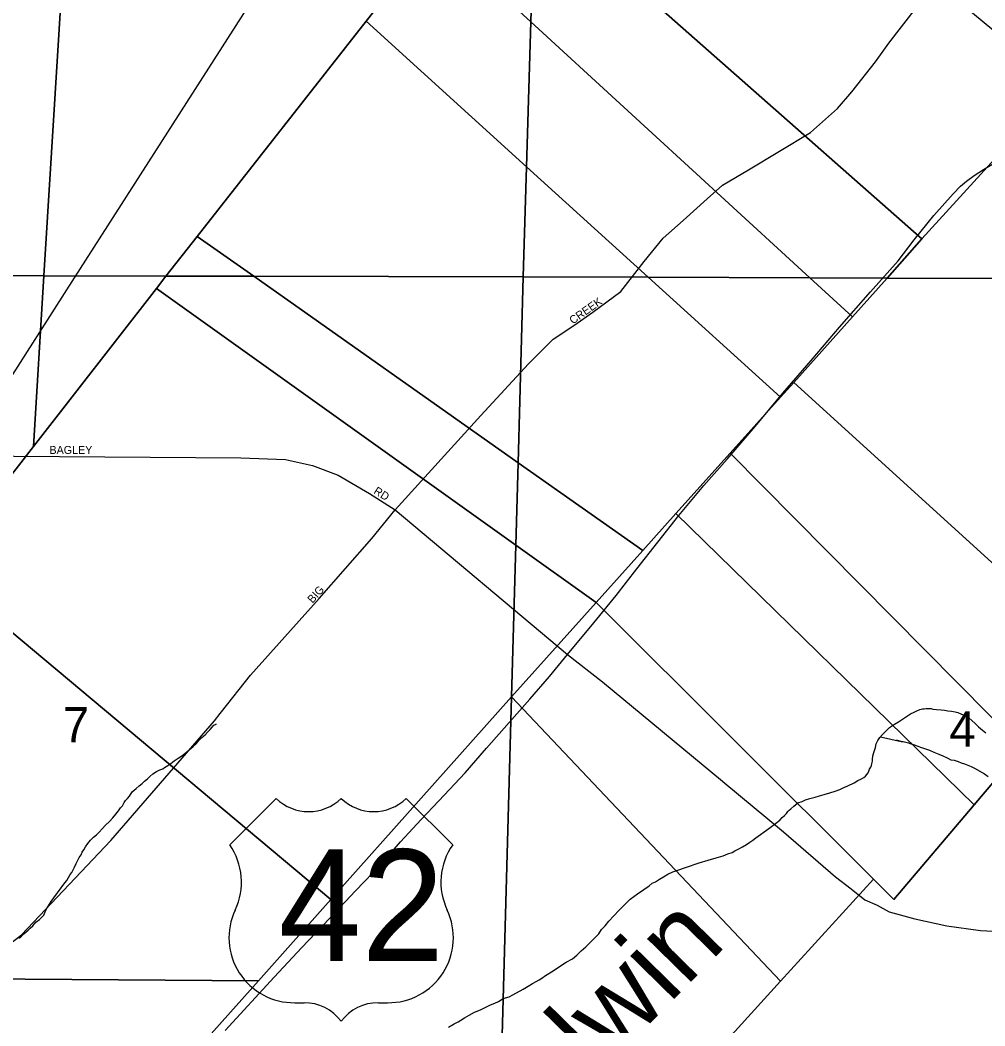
# Model space of a CAD drawing. Extents: x 2010165 to 2382125, y 1060529 to 1407316.
# Drawn here: x 2156190 to 2162213, y 1225499 to 1231781 of the extents above; entities that cross this region are included whole.
import ezdxf

# ---------------------------------------------------------------- set-up
doc = ezdxf.new("R2010")
doc.units = 0
for name, color, linetype in [('GM_X_City_Street', 7, 'Continuous'), ('GM_X_City_Street_Text', 7, 'Continuous'), ('GM_X_Minor_River', 7, 'Continuous'), ('GM_X_Minor_River_Text', 7, 'Continuous'), ('GM_X_Rail_Line', 7, 'Continuous'), ('GM_X_Section', 7, 'Continuous'), ('GM_X_Section_Text', 7, 'Continuous'), ('GM_X_US_Location', 7, 'Continuous'), ('GM_X_US_Route', 7, 'Continuous'), ('GM_X_US_Shield', 7, 'Continuous')]:
    doc.layers.add(name, color=color, linetype=linetype)

msp = doc.modelspace()

# ---------------------------------------------------------------- linework, layer by layer
at = {"layer": 'GM_X_City_Street'}
for points in [[(2162868.4, 1231219), (2161945, 1231985), (2159433.3, 1234116.7), (2159331.7, 1234201.2), (2159308.2, 1234295.5), (2159312.2, 1234628.9)], [(2158532.2, 1228721.7), (2159067.2, 1229312.4), (2159364.5, 1229634.1), (2159517.2, 1229787.9), (2159646.5, 1229873.4), (2159765.8, 1229956.7), (2159940.7, 1230086.7), (2160085.1, 1230272.6), (2160205.5, 1230420.1), (2160330.4, 1230530.2), (2160478.6, 1230665.5), (2160575.8, 1230750.5), (2160736.6, 1230846.7), (2161125.6, 1231078.8), (2161292.5, 1231230.1), (2161383.6, 1231333.3), (2161529.4, 1231521.5), (2161614.5, 1231636.9), (2161785.5, 1231859.7)], [(2155300.7, 1229064.8), (2157567.5, 1229047.7), (2157845.6, 1229036.3), (2158015.9, 1228999.7), (2158174.4, 1228939), (2158371.4, 1228824.5), (2158532.2, 1228721.7), (2159607.8, 1227818.3)], [(2157447.3, 1227460.9), (2157629, 1227690.4), (2158056.9, 1228169.7), (2158385.7, 1228543.8), (2158532.2, 1228721.7)], [(2159607.8, 1227818.3), (2159825.2, 1227648.6), (2160575.7, 1227027.8), (2160577.2, 1227026.5)], [(2154223.5, 1224477), (2154223.5, 1224477), (2154349.7, 1224803), (2154466.7, 1225003.3), (2154573.1, 1225171.7), (2154728.5, 1225408.9), (2154883.1, 1225544.5), (2154998.2, 1225623.4), (2155146.2, 1225694.6), (2155257.3, 1225724.1), (2155928.2, 1225891.4), (2156067.7, 1225965.8), (2156198.3, 1226068.3), (2156755.8, 1226656.4), (2157403.4, 1227405.5), (2157439.3, 1227450.9), (2157447.3, 1227460.9)], [(2160577.2, 1227026.5), (2160957, 1226712.3), (2161281.4, 1226430.6), (2161378, 1226355.2), (2161464.6, 1226285.8), (2161540.9, 1226252.4), (2161615.2, 1226211), (2161775.6, 1226168.4), (2161976, 1226124.1), (2162186.2, 1226096), (2162428.3, 1226082.2), (2162702.2, 1226094.8), (2164457.5, 1226169.3), (2164865.3, 1226193.2)]]:
    msp.add_lwpolyline(points, dxfattribs=at)
at = {"layer": 'GM_X_Minor_River'}
for points in [[(2160206.1, 1226429.7), (2160234, 1226446.1), (2160265.8, 1226460.5), (2160301.7, 1226475), (2160343.6, 1226487.6), (2160429.4, 1226516.7), (2160485.3, 1226533.4), (2160535.2, 1226548.1), (2160579.1, 1226560.6), (2160609, 1226573.1), (2160634.9, 1226581.4), (2160652.8, 1226593.6), (2160676.7, 1226606), (2160700.5, 1226618.3), (2160724.4, 1226632.6), (2160746.2, 1226647), (2160764.1, 1226659.2), (2160784, 1226673.5), (2160865.3, 1226732.7), (2160907, 1226763.3), (2160932.8, 1226783.7), (2160948.6, 1226799.9), (2160962.4, 1226814.1), (2160974.3, 1226826.3), (2160982.2, 1226838.4), (2160992.1, 1226846.6), (2161002, 1226854.8), (2161019.8, 1226871), (2161045.6, 1226893.4), (2161073.5, 1226901.8), (2161093.4, 1226912.1), (2161121.3, 1226920.4), (2161153.3, 1226928.8), (2161181.2, 1226935.2), (2161209.2, 1226943.6), (2161245.1, 1226954), (2161279, 1226964.5), (2161307, 1226974.8), (2161332.8, 1226987.2), (2161358.7, 1226999.6), (2161396.5, 1227018.1), (2161420.4, 1227032.4), (2161442.3, 1227042.7), (2161458.2, 1227050.9), (2161468.1, 1227059.1), (2161476, 1227069.2), (2161483.9, 1227079.3), (2161489.8, 1227089.5), (2161493.6, 1227103.5), (2161501.5, 1227115.7), (2161505.3, 1227125.8), (2161507.2, 1227135.8), (2161511, 1227151.9), (2161510.8, 1227163.9), (2161514.6, 1227186.1), (2161522.2, 1227212.2), (2161529.9, 1227238.4), (2161535.6, 1227260.6), (2161545.4, 1227280.8), (2161557.1, 1227301), (2161574.9, 1227319.2), (2161590.7, 1227335.5), (2161618.4, 1227363.9), (2161648.2, 1227384.3), (2161674.1, 1227398.7), (2161749.5, 1227447.8), (2161771.5, 1227458.1), (2161789.4, 1227466.3), (2161807.3, 1227474.6), (2161823.3, 1227478.8), (2161835.3, 1227478.9), (2161847.3, 1227481.1), (2161865.3, 1227481.3), (2161877.3, 1227481.4), (2161889.4, 1227477.6), (2161911.5, 1227475.8), (2161939.5, 1227474.2), (2161961.6, 1227470.4), (2161981.7, 1227466.7), (2162005.8, 1227465), (2162027.9, 1227461.2), (2162043.9, 1227457.4), (2162064.1, 1227447.6), (2162092.3, 1227435.9), (2162112.5, 1227424.1), (2162132.8, 1227406.3), (2162153, 1227388.5), (2162173.4, 1227366.7), (2162197.7, 1227346.9), (2162219.9, 1227329.1)], [(2156966.7, 1227028.2), (2156984.6, 1227042.4), (2157000.4, 1227056.7), (2157018.2, 1227073), (2157040.1, 1227087.3), (2157061.9, 1227099.6), (2157079.9, 1227105.8), (2157091.8, 1227114), (2157111.7, 1227126.3), (2157129.6, 1227138.5), (2157151.4, 1227154.8), (2157177.2, 1227171.2), (2157199.1, 1227185.5), (2157218.9, 1227199.8), (2157270.4, 1227244.6), (2157288.2, 1227260.8), (2157306, 1227281.1), (2157323.8, 1227301.4), (2157345.6, 1227317.7), (2157361.4, 1227336), (2157377.2, 1227350.2), (2157389.1, 1227364.4), (2157398.9, 1227376.6), (2157412.8, 1227384.8), (2157410.8, 1227384.7), (2157410.9, 1227382.7)], [(2161561, 1227305), (2161689.7, 1227276.5), (2161661.5, 1227284.2), (2161689.7, 1227276.5), (2161703.7, 1227274.6), (2161719.8, 1227270.8), (2161735.9, 1227267), (2161752, 1227261.2), (2161774.1, 1227255.4), (2161794.3, 1227245.7), (2161818.4, 1227237.9), (2161842.6, 1227230.2), (2161866.7, 1227220.5), (2161894.9, 1227208.8), (2161925.1, 1227197.1), (2161951.3, 1227185.4), (2161977.5, 1227173.7), (2162001.7, 1227161.9), (2162021.8, 1227158.1), (2162045.9, 1227150.4), (2162066.1, 1227142.6), (2162086.2, 1227136.9), (2162106.4, 1227127.1), (2162128.5, 1227119.3), (2162148.7, 1227109.6), (2162211.2, 1227074.2), (2162233.5, 1227056.4)], [(2156182.2, 1226047.4), (2156198, 1226059.7), (2156211.9, 1226073.9), (2156227.7, 1226086.1), (2156239.6, 1226096.3), (2156251.5, 1226110.5), (2156269.3, 1226124.8), (2156287, 1226147.1), (2156310.9, 1226163.4), (2156324.7, 1226177.6), (2156338.5, 1226191.8), (2156342.4, 1226201.9), (2156352.1, 1226226.1), (2156383.5, 1226276.6), (2156399.3, 1226298.9), (2156468.2, 1226392.1), (2156482, 1226408.3), (2156491.7, 1226426.4), (2156501.5, 1226444.6), (2156511.4, 1226456.8), (2156521.2, 1226473), (2156529, 1226491.1), (2156538.7, 1226513.3), (2156548.5, 1226529.5), (2156558.2, 1226551.7), (2156570, 1226567.9), (2156577.8, 1226584), (2156587.7, 1226598.2), (2156597.4, 1226618.4), (2156613.2, 1226638.6), (2156629, 1226658.9), (2156646.7, 1226677.1), (2156666.6, 1226693.4), (2156682.4, 1226709.7), (2156702.1, 1226730), (2156721.9, 1226752.3), (2156747.6, 1226776.7), (2156767.4, 1226799), (2156787.1, 1226821.3), (2156802.9, 1226841.6), (2156816.6, 1226861.8), (2156828.5, 1226874), (2156840.2, 1226894.2), (2156848.1, 1226906.3), (2156860, 1226918.5), (2156871.8, 1226934.7), (2156889.5, 1226961), (2156913.2, 1226981.4), (2156933.1, 1226997.7), (2156950.9, 1227013.9), (2156966.7, 1227028.2)], [(2158864, 1225492.3), (2158899.8, 1225512.8), (2158923.7, 1225525.1), (2158941.6, 1225535.4), (2158963.5, 1225549.7), (2158993.3, 1225566.1), (2159027.1, 1225584.6), (2159065, 1225599.1), (2159096.8, 1225615.5), (2159126.7, 1225630), (2159152.6, 1225640.3), (2159176.5, 1225652.6), (2159206.3, 1225671.1), (2159242.2, 1225681.5), (2159266.1, 1225693.8), (2159329.8, 1225728.8), (2159361.6, 1225747.2), (2159389.4, 1225763.6), (2159411.3, 1225775.9), (2159431.2, 1225786.2), (2159447.1, 1225798.4), (2159470.9, 1225814.7), (2159518.6, 1225843.4), (2159558.3, 1225870), (2159600, 1225896.6), (2159637.8, 1225919.1), (2159665.6, 1225941.5), (2159693.3, 1225967.9), (2159721, 1225992.4), (2159742.7, 1226014.7), (2159762.5, 1226035), (2159784.3, 1226055.3), (2159802.1, 1226073.6), (2159819.7, 1226101.9), (2159843.5, 1226124.3), (2159865.2, 1226152.6), (2159896.8, 1226187.1), (2159928.4, 1226219.6), (2159960, 1226252.1), (2159999.6, 1226290.7), (2160045.3, 1226323.4), (2160082.9, 1226351.9), (2160116.7, 1226374.4), (2160136.5, 1226390.7), (2160156.5, 1226399), (2160182.3, 1226415.3), (2160206.1, 1226429.7)]]:
    msp.add_lwpolyline(points, dxfattribs=at)
at = {"layer": 'GM_X_Rail_Line'}
msp.add_lwpolyline([(2152659, 1224128.4), (2152739.6, 1224246.9), (2152909.8, 1224516.9), (2153135.7, 1224869.5), (2153696.1, 1225746.1), (2153852.4, 1225988.7), (2154336.9, 1226746.4), (2154804.9, 1227475), (2154949.8, 1227703.5), (2155203.2, 1228100.3), (2155761.5, 1228971.2), (2156480.3, 1230096.1), (2157742.6, 1232068.2), (2160262.5, 1236005.3), (2160720.5, 1236722.8), (2161364.8, 1237726.8), (2162140.1, 1238942.9), (2162984.3, 1240258.6), (2165607, 1244357.2), (2165822.2, 1244694.3), (2166159.2, 1245221.1), (2166502.4, 1245756.1), (2166780.6, 1246192.6), (2167540, 1247377.8)], dxfattribs=at)
at = {"layer": 'GM_X_Section'}
for points in [[(2159417.7, 1233134.5), (2159997.2, 1233872.9), (2163015.7, 1231555.2), (2162360.8, 1231008.9), (2161818.7, 1230414.8), (2159400.5, 1232548.2)], [(2159138.7, 1232779.1), (2159400.5, 1232548.2), (2159377.7, 1231770.4), (2158778.4, 1232320)], [(2159377.7, 1231770.4), (2159400.5, 1232548.2), (2161818.7, 1230414.8), (2161604.3, 1230169.9), (2161121.1, 1230171.6)], [(2158620.5, 1232118.8), (2158778.4, 1232320), (2159377.7, 1231770.4), (2159351.2, 1230865.6), (2158350.2, 1231774.5)], [(2156456.2, 1232094.9), (2158620.5, 1232118.8), (2158350.2, 1231774.5), (2157294.8, 1230429.8), (2157100.3, 1230181.9), (2156338.3, 1230183.2)], [(2154026.7, 1232068), (2156456.2, 1232094.9), (2156338.3, 1230183.2), (2153937.9, 1230187.4)], [(2158350.2, 1231774.5), (2159351.2, 1230865.6), (2159331, 1230177.9), (2157647.8, 1230180.9), (2157294.8, 1230429.8)], [(2159351.2, 1230865.6), (2159377.7, 1231770.4), (2161121.1, 1230171.6), (2160111.4, 1230175.2)], [(2161818.7, 1230414.8), (2162360.8, 1231008.9), (2163222.3, 1230164.2), (2161604.3, 1230169.9)], [(2159331, 1230177.9), (2159351.2, 1230865.6), (2160111.4, 1230175.2)], [(2157294.8, 1230429.8), (2157647.8, 1230180.9), (2157100.3, 1230181.9)], [(2153937.9, 1230187.4), (2156338.3, 1230183.2), (2156272.6, 1229118.6), (2155759.2, 1228459.1), (2155751, 1228281.1), (2155636.1, 1225795.5), (2157678.6, 1225781.7), (2157120.7, 1225155.3), (2156676.4, 1224704.2), (2153680, 1224728.2)], [(2156338.3, 1230183.2), (2157100.3, 1230181.9), (2157040.2, 1230104.6), (2156272.6, 1229118.6)], [(2157100.3, 1230181.9), (2157647.8, 1230180.9), (2159298.8, 1229016.9), (2159284.5, 1228500.8), (2157040.2, 1230104.6)], [(2157647.8, 1230180.9), (2159331, 1230177.9), (2159298.8, 1229016.9)], [(2159331, 1230177.9), (2160111.4, 1230175.2), (2160936.8, 1229425.7), (2160623, 1229076), (2160284.7, 1228699), (2160077.4, 1228468), (2159298.8, 1229016.9)], [(2160111.4, 1230175.2), (2161121.1, 1230171.6), (2161387.2, 1229927.5), (2161019.8, 1229518.1), (2160936.8, 1229425.7)], [(2161604.3, 1230169.9), (2163222.3, 1230164.2), (2164163.6, 1229262.5), (2162917.8, 1227792.4), (2161019.8, 1229518.1), (2161387.2, 1229927.5)], [(2161121.1, 1230171.6), (2161604.3, 1230169.9), (2161387.2, 1229927.5)], [(2157040.2, 1230104.6), (2159284.5, 1228500.8), (2159258.2, 1227553.7), (2158130.5, 1226289.2), (2155751, 1228281.1), (2155759.2, 1228459.1), (2156272.6, 1229118.6)], [(2164892.6, 1229601.3), (2164886.4, 1228716.3), (2164890.7, 1226190.3), (2164893.3, 1224650.6), (2161969.6, 1224667.8), (2159940.1, 1224679.7), (2160937.9, 1225778.1), (2161517.6, 1226416), (2161645.8, 1226288.2), (2162145.6, 1226879.2), (2162446.4, 1227234.8), (2162917.8, 1227792.4), (2164163.6, 1229262.5), (2164602, 1229623.7)], [(2161019.8, 1229518.1), (2162917.8, 1227792.4), (2162446.4, 1227234.8), (2160623, 1229076), (2160936.8, 1229425.7)], [(2160623, 1229076), (2162446.4, 1227234.8), (2162145.6, 1226879.2), (2160284.7, 1228699)], [(2159298.8, 1229016.9), (2160077.4, 1228468), (2159785.5, 1228142.8), (2159284.5, 1228500.8)], [(2160284.7, 1228699), (2162145.6, 1226879.2), (2161645.8, 1226288.2), (2161517.6, 1226416), (2159785.5, 1228142.8), (2160077.4, 1228468)], [(2159785.5, 1228142.8), (2159258.2, 1227553.7), (2159284.5, 1228500.8)], [(2158130.5, 1226289.2), (2157678.6, 1225781.7), (2155636.1, 1225795.5), (2155751, 1228281.1)], [(2159785.5, 1228142.8), (2161517.6, 1226416), (2160937.9, 1225778.1), (2159258.2, 1227553.7)], [(2159258.2, 1227553.7), (2159178.7, 1224684.2), (2157758.6, 1224695.5), (2157120.7, 1225155.3), (2157678.6, 1225781.7), (2158130.5, 1226289.2)], [(2159258.2, 1227553.7), (2160937.9, 1225778.1), (2159940.1, 1224679.7), (2159178.7, 1224684.2)]]:
    msp.add_lwpolyline(points, close=True, dxfattribs=at)
at = {"layer": 'GM_X_US_Route'}
for points in [[(2159607.8, 1227818.3), (2159771.1, 1228017.5), (2159910.6, 1228186.6), (2160040.1, 1228353.5), (2160303, 1228687.6), (2160458.4, 1228874.7), (2160603.9, 1229039.8), (2160779.2, 1229243.1), (2160952.6, 1229450.4), (2161128, 1229655.7), (2161305.3, 1229863), (2161498.6, 1230084.4), (2161671.2, 1230278.6), (2161771, 1230409.3), (2161894.7, 1230560), (2162014.5, 1230696.8), (2162060.4, 1230745), (2162098.4, 1230775.2), (2162146.4, 1230811.5), (2162204.4, 1230847.8), (2162298.4, 1230904.2), (2162480.4, 1231003.1), (2162676.4, 1231110), (2162868.4, 1231219)], [(2157469.1, 1225470.7), (2157776, 1225803.1), (2157949.4, 1225988.4), (2158120.8, 1226169.6), (2158284.3, 1226342.7), (2158447.8, 1226513.9), (2158565.4, 1226648.7), (2158693, 1226787.6), (2158804.6, 1226904.4), (2158968.1, 1227079.6), (2159101.6, 1227234.6), (2159243.1, 1227393.6), (2159372.6, 1227540.5), (2159494.2, 1227681.4), (2159607.8, 1227818.3)]]:
    msp.add_lwpolyline(points, dxfattribs=at)
at = {"layer": 'GM_X_US_Shield'}
for p, q in [((2157788.2, 1226920.3), (2157498.2, 1226630.2)), ((2158890.4, 1226630.2), (2158600.3, 1226920.3)), ((2157904.2, 1225644.1), (2157962.2, 1225644.1)), ((2158426.3, 1225644.1), (2158484.3, 1225644.1))]:
    msp.add_line(p, q, dxfattribs=at)
for centre, radius, start, end in [((2157991.2, 1227127.4), 290, 225.573, 314.427), ((2158397.3, 1227127.4), 290, 225.573, 314.427), ((2157165.5, 1226397.3), 406.1, 334.54712, 35.00093), ((2159223, 1226397.3), 406.1, 144.99907, 205.45288), ((2157899.7, 1226050.1), 406.1, 154.83192, 270.63826), ((2158488.8, 1226050.1), 406.1, 269.36174, 25.16808), ((2157962.2, 1225354.1), 290, 36.8699, 90), ((2158426.3, 1225354.1), 290, 90, 143.1301)]:
    msp.add_arc(centre, radius, start, end, dxfattribs=at)

# ---------------------------------------------------------------- texts
at = {"layer": 'GM_X_City_Street_Text'}
for s, rotation, p in [('CREEK', 35.39409, (2159640.9, 1229879.3)), ('BAGLEY', 0.00001, (2156372.7, 1229071.4)), ('RD', 327.98725, (2158392.8, 1228827.9)), ('BIG', 48.18016, (2158015.6, 1228135.4))]:
    msp.add_text(s, height=50, rotation=rotation, dxfattribs=at).set_placement(p)
at = {"layer": 'GM_X_Minor_River_Text'}
msp.add_text('Baldwin', height=500.28, rotation=45.53118, dxfattribs=at).set_placement((2158965.5, 1224334.8))
at = {"layer": 'GM_X_Section_Text'}
for s, p in [('7', (2156456.3, 1227269.9)), ('4', (2161991.5, 1227242.3))]:
    msp.add_text(s, height=221, rotation=0.00001, dxfattribs=at).set_placement(p)
at = {"layer": 'GM_X_US_Location'}
for s in ['/', '0']:
    msp.add_text(s, height=1, dxfattribs=at).set_placement((2158193.9, 1226247.7))
msp.add_text('42', height=1, rotation=0.00001, dxfattribs=at).set_placement((2157987.5, 1226040.7))
at = {"layer": 'GM_X_US_Shield'}
msp.add_text('42', height=696.1, dxfattribs=at).set_placement((2157802.4, 1225905.1))

doc.saveas('drawing.dxf')
